Omron CX-Programmer project NewProject (CX-Programmer 8.01)

# PLC NewPLC1: CP1L M

## Global symbols (name address type ; comment)
AlarmAckCRT 4000.06 BOOL
AlarmActive 100.03 BOOL
CloseDischargeValueTimer T3 UINT_BCD
CloseDischargeValveCRT 4000.03 BOOL
CloseTankValueTimer T5 UINT_BCD
CloseTankValveCRT 4000.05 BOOL
CloseTankValveONS 3801.01 BOOL
DischargeValveCloseTimerComplete T0003 BOOL
DischargeValveClosed 3800.09 BOOL
DischargeValveOpenTimerComplete T0002 BOOL
DischargeValveOpened 3800.08 BOOL
DischargeValveTravel 3800.10 BOOL
OpenDischargeValueTimer T2 UINT_BCD
OpenDischargeValve 100.02 BOOL
OpenDischargeValveCRT 4000.02 BOOL
OpenDischargeValveLatch 3800.07 BOOL
OpenTankValueTimer T4 UINT_BCD
OpenTankValve 100.01 BOOL
OpenTankValveCRT 4000.04 BOOL
OpenTankValveONS 3801.00 BOOL
PumpFailedToStartFault 3800.03 BOOL
PumpFailedToStartONS 3800.05 BOOL
PumpFailedToStopFault 3800.04 BOOL
PumpFailedToStopONS 3800.06 BOOL
PumpPressure D23 INT
PumpRunLatch 3800.01 BOOL
PumpRunning 0.00 BOOL
PumpStartONS 3800.00 BOOL
PumpStartStopPB 0.02 BOOL
PumpStartTimer T0 UINT_BCD
PumpStartTimerComplete T0000 BOOL
PumpStopONS 3800.02 BOOL
PumpStopTimer T1 UINT_BCD
PumpStopTimerComplete T0001 BOOL
StartPump 100.00 BOOL
StartPumpCRT 4000.00 BOOL
StopPumpCRT 4000.01 BOOL
TankLevel D24 INT
TankLevelHi 3801.04 BOOL
TankLevelHiHi 3801.05 BOOL
TankLevelLo 3801.02 BOOL
TankLevelLoLo 3801.03 BOOL
TankOutletFlow D25 INT
TankValveCloseTimerComplete T0005 BOOL
TankValveClosed 0.01 BOOL
TankValveFailedToCloseFault 3800.13 BOOL
TankValveFailedToCloseONS 3800.15 BOOL
TankValveFailedToOpenFault 3800.12 BOOL
TankValveFailedToOpenONS 3800.14 BOOL
TankValveOpenClosePB 0.03 BOOL
TankValveOpenLatch 3800.11 BOOL
TankValveOpenTimerComplete T0004 BOOL

## Program Main_Program (cyclic task 0)

### Section PumpLogic

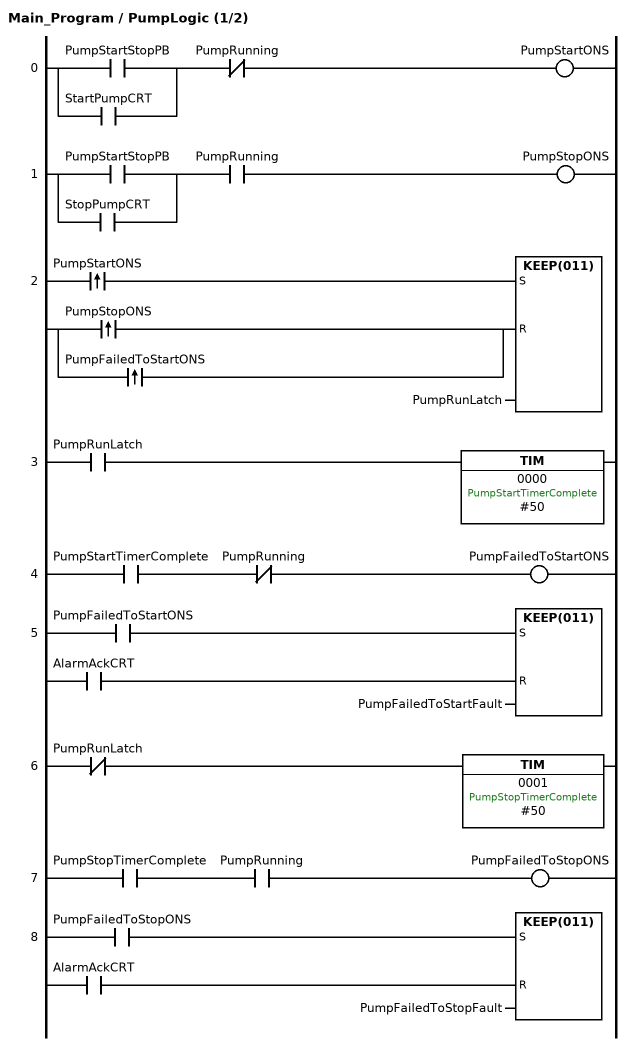
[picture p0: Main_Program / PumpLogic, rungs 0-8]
; rung 0
LD PumpStartStopPB
OR StartPumpCRT
ANDNOT PumpRunning
OUT PumpStartONS
; rung 1
LD PumpStartStopPB
OR StopPumpCRT
AND PumpRunning
OUT PumpStopONS
; rung 2
@LD PumpStartONS
@LD PumpStopONS
@OR PumpFailedToStartONS
KEEP(011) PumpRunLatch
; rung 3
LD PumpRunLatch
TIM 0000 #50  ; PumpStartTimerComplete
; rung 4
LD PumpStartTimerComplete
ANDNOT PumpRunning
OUT PumpFailedToStartONS
; rung 5
LD PumpFailedToStartONS
LD AlarmAckCRT
KEEP(011) PumpFailedToStartFault
; rung 6
LDNOT PumpRunLatch
TIM 0001 #50  ; PumpStopTimerComplete
; rung 7
LD PumpStopTimerComplete
AND PumpRunning
OUT PumpFailedToStopONS
; rung 8
LD PumpFailedToStopONS
LD AlarmAckCRT
KEEP(011) PumpFailedToStopFault

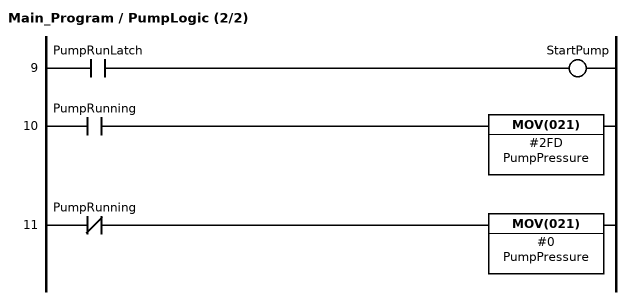
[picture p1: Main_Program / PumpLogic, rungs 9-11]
; rung 9
LD PumpRunLatch
OUT StartPump
; rung 10
LD PumpRunning
MOV(021) #2FD PumpPressure
; rung 11
LDNOT PumpRunning
MOV(021) #0 PumpPressure

### Section DischargeValve

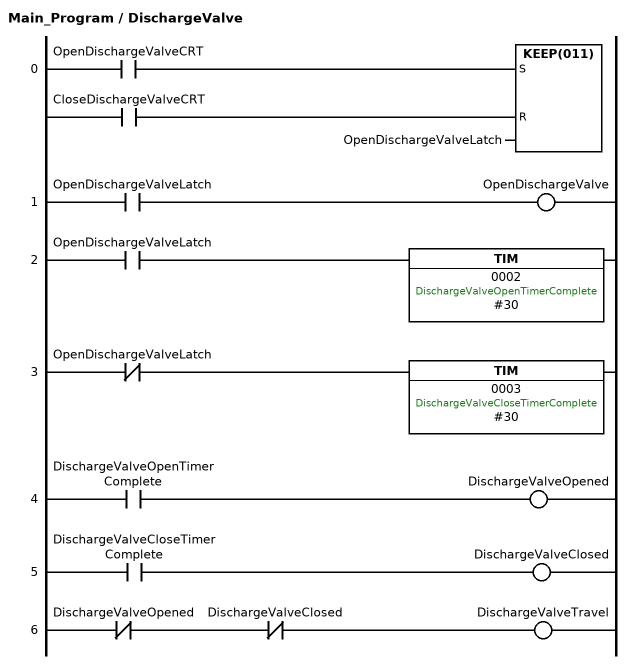
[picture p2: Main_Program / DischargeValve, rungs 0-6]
; rung 0
LD OpenDischargeValveCRT
LD CloseDischargeValveCRT
KEEP(011) OpenDischargeValveLatch
; rung 1
LD OpenDischargeValveLatch
OUT OpenDischargeValve
; rung 2
LD OpenDischargeValveLatch
TIM 0002 #30  ; DischargeValveOpenTimerComplete
; rung 3
LDNOT OpenDischargeValveLatch
TIM 0003 #30  ; DischargeValveCloseTimerComplete
; rung 4
LD DischargeValveOpenTimerComplete
OUT DischargeValveOpened
; rung 5
LD DischargeValveCloseTimerComplete
OUT DischargeValveClosed
; rung 6
LDNOT DischargeValveOpened
ANDNOT DischargeValveClosed
OUT DischargeValveTravel

### Section TankValve

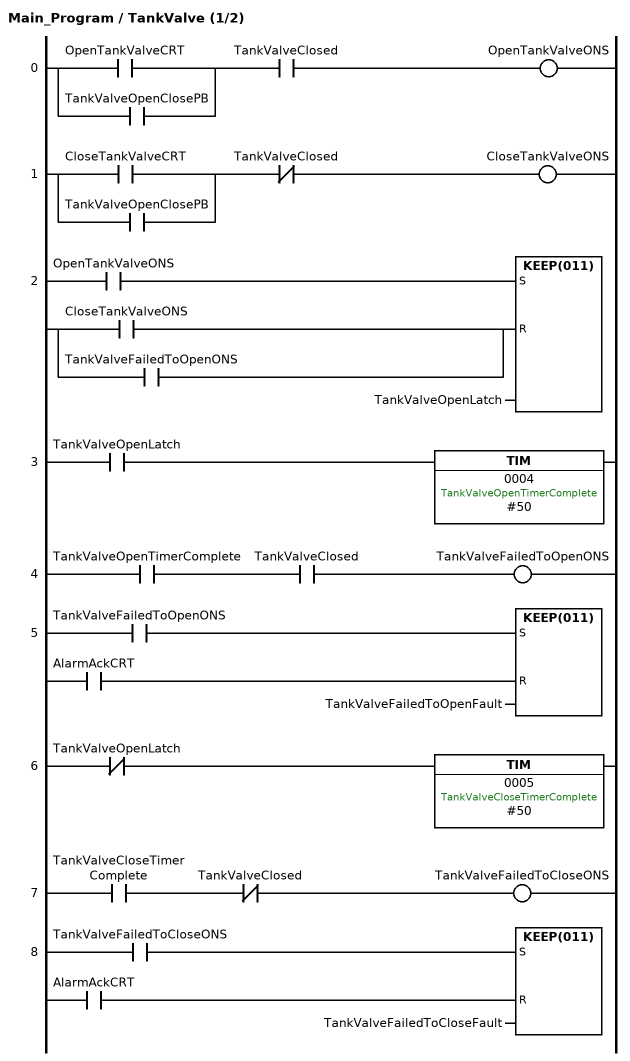
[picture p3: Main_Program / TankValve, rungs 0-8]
; rung 0
LD OpenTankValveCRT
OR TankValveOpenClosePB
AND TankValveClosed
OUT OpenTankValveONS
; rung 1
LD CloseTankValveCRT
OR TankValveOpenClosePB
ANDNOT TankValveClosed
OUT CloseTankValveONS
; rung 2
LD OpenTankValveONS
LD CloseTankValveONS
OR TankValveFailedToOpenONS
KEEP(011) TankValveOpenLatch
; rung 3
LD TankValveOpenLatch
TIM 0004 #50  ; TankValveOpenTimerComplete
; rung 4
LD TankValveOpenTimerComplete
AND TankValveClosed
OUT TankValveFailedToOpenONS
; rung 5
LD TankValveFailedToOpenONS
LD AlarmAckCRT
KEEP(011) TankValveFailedToOpenFault
; rung 6
LDNOT TankValveOpenLatch
TIM 0005 #50  ; TankValveCloseTimerComplete
; rung 7
LD TankValveCloseTimerComplete
ANDNOT TankValveClosed
OUT TankValveFailedToCloseONS
; rung 8
LD TankValveFailedToCloseONS
LD AlarmAckCRT
KEEP(011) TankValveFailedToCloseFault

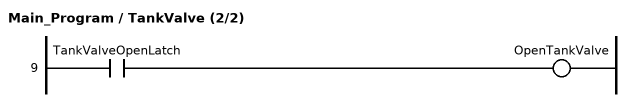
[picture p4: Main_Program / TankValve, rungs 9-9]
; rung 9
LD TankValveOpenLatch
OUT OpenTankValve

### Section TankFlow

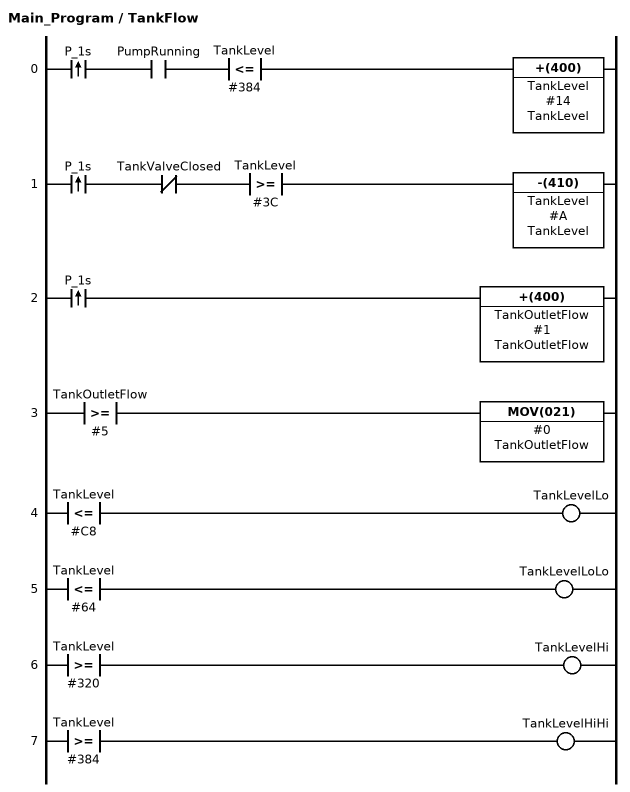
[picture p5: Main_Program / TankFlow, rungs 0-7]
; rung 0
@LD P_1s
AND PumpRunning
AND<=S(317) TankLevel #384
+(400) TankLevel #14 TankLevel
; rung 1
@LD P_1s
ANDNOT TankValveClosed
AND>=S(327) TankLevel #3C
-(410) TankLevel #A TankLevel
; rung 2
@LD P_1s
+(400) TankOutletFlow #1 TankOutletFlow
; rung 3
LD>=S(327) TankOutletFlow #5
MOV(021) #0 TankOutletFlow
; rung 4
LD<=S(317) TankLevel #C8
OUT TankLevelLo
; rung 5
LD<=S(317) TankLevel #64
OUT TankLevelLoLo
; rung 6
LD>=S(327) TankLevel #320
OUT TankLevelHi
; rung 7
LD>=S(327) TankLevel #384
OUT TankLevelHiHi

### Section Alarming

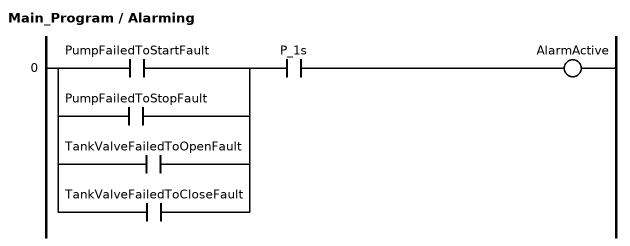
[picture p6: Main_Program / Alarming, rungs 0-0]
; rung 0
LD PumpFailedToStartFault
OR PumpFailedToStopFault
OR TankValveFailedToOpenFault
OR TankValveFailedToCloseFault
AND P_1s
OUT AlarmActive
; rung 1
END(001)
